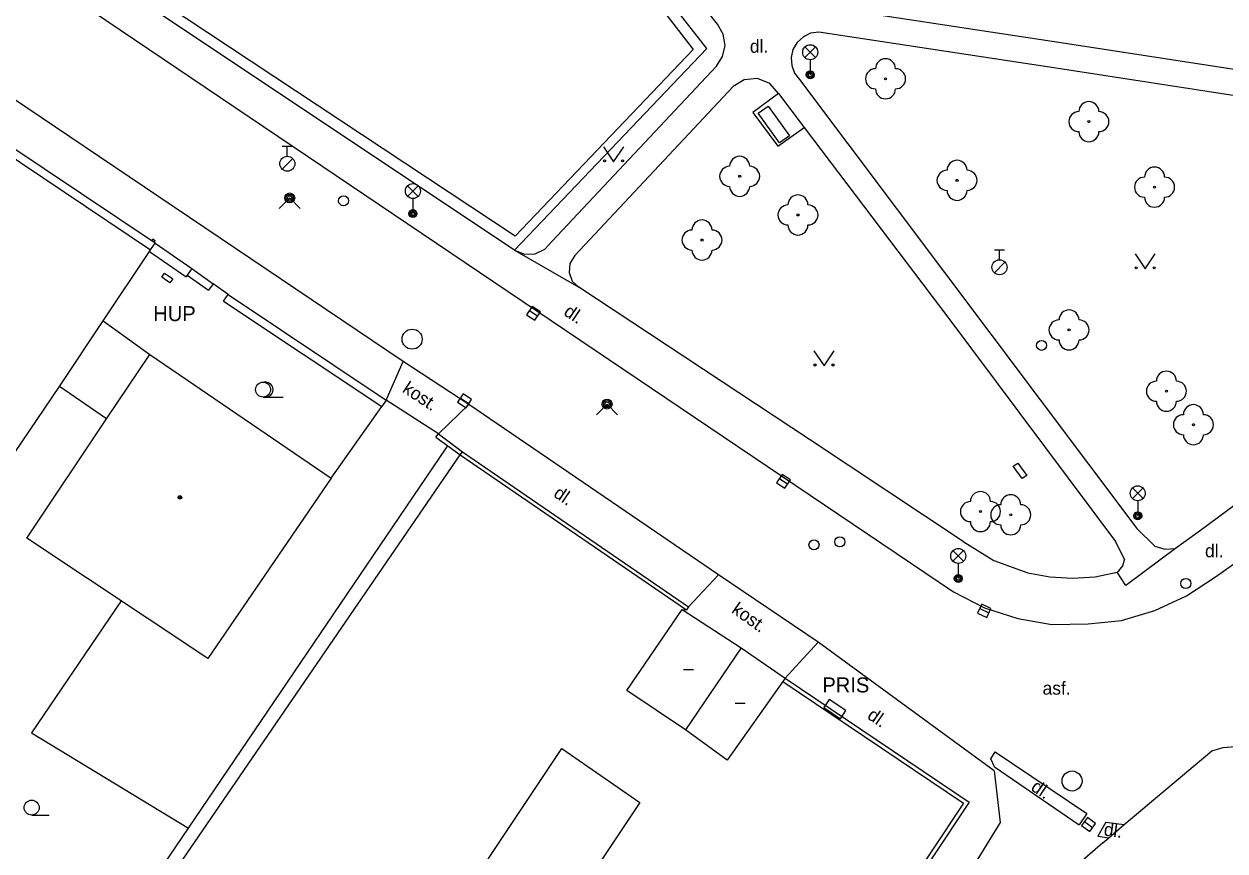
# Model space of a CAD drawing. Extents: x -600391 to -599491, y -1160176 to -1159402.
# Drawn here: x -600305.1 to -600245.1, y -1160114.6 to -1160073.3 of the extents above; entities that cross this region are included whole.
import ezdxf

# ---------------------------------------------------------------- set-up
doc = ezdxf.new("R2010")
doc.units = 0
for name, color, linetype in [('Level 10', 7, 'Continuous'), ('Level 11', 7, 'Continuous'), ('Level 22', 7, 'Continuous'), ('Level 24', 7, 'Continuous'), ('Level 27', 7, 'Continuous'), ('Level 28', 7, 'Continuous'), ('Level 31', 7, 'Continuous'), ('Level 33', 7, 'Continuous'), ('Level 36', 7, 'Continuous'), ('Level 39', 7, 'Continuous'), ('Level 40', 7, 'Continuous'), ('Level 41', 7, 'Continuous'), ('Level 5', 7, 'Continuous'), ('Level 7', 7, 'Continuous'), ('Level 8', 7, 'Continuous')]:
    doc.layers.add(name, color=color, linetype=linetype)

msp = doc.modelspace()

# ---------------------------------------------------------------- linework, layer by layer
at = {"layer": 'Level 10'}
for points in [[(-600391.008, -1160012.297), (-600389.33, -1160013.43), (-600385.97, -1160015.7), (-600380.12, -1160019.65), (-600376.77, -1160021.91), (-600369.66, -1160026.71), (-600367.22, -1160028.36), (-600362.33, -1160031.66), (-600357.66, -1160034.81), (-600345.98, -1160042.7), (-600342.95, -1160044.75), (-600341.58, -1160045.67), (-600338.1, -1160048.02), (-600335.29, -1160049.92), (-600325.8, -1160056.33), (-600315.13, -1160063.54), (-600309.38, -1160067.42), (-600304.6, -1160070.65), (-600301.7, -1160072.61), (-600258.67, -1160101.64)], [(-600286.14, -1160090.13), (-600298.33, -1160081.92), (-600327.82, -1160062.03), (-600331.39, -1160059.62), (-600334.69, -1160057.39), (-600338.31, -1160054.95), (-600376.99, -1160028.86)], [(-600256.63, -1160110.57), (-600265.43, -1160104.15), (-600270.39, -1160100.79), (-600282.86, -1160092.29), (-600286.14, -1160090.13)], [(-600245.58, -1160100.88), (-600242.67, -1160098.83)], [(-600258.67, -1160101.64), (-600257.12, -1160102.43), (-600255.46, -1160102.97), (-600253.75, -1160103.26), (-600251.95, -1160103.24), (-600250.28, -1160103.06), (-600248.61, -1160102.57), (-600247.03, -1160101.84), (-600245.58, -1160100.88)], [(-600245.77, -1160109.57), (-600245.2, -1160109.4), (-600244.19, -1160109.32)], [(-600251.22, -1160114.16), (-600250.92, -1160113.91), (-600250.14, -1160113.25), (-600245.77, -1160109.57)], [(-600256.63, -1160110.57), (-600256.34, -1160113.16), (-600267.47, -1160131.26)], [(-600251.22, -1160114.16), (-600254.94, -1160117.42), (-600259.81, -1160125.54), (-600260.41, -1160126.54), (-600260.93, -1160128.09), (-600260.66, -1160129.14), (-600260.06, -1160129.54), (-600259.92, -1160129.54)]]:
    msp.add_lwpolyline(points, dxfattribs=at)
at = {"layer": 'Level 11'}
for points in [[(-600270.44, -1160073.3), (-600270.89, -1160072.72), (-600279.69, -1160061.33), (-600280.7, -1160060.03), (-600290, -1160048.14)], [(-600268.21, -1160071.92), (-600253.19, -1160074.23), (-600244.65, -1160075.54), (-600243.72, -1160075.27)], [(-600270.5, -1160075.39), (-600270.19, -1160074.91), (-600270.07, -1160074.36), (-600270.16, -1160073.79), (-600270.44, -1160073.3)], [(-600265.39, -1160073.69), (-600265.8, -1160073.75), (-600266.16, -1160073.92), (-600266.47, -1160074.2), (-600266.68, -1160074.55), (-600266.77, -1160074.95), (-600266.74, -1160075.35), (-600266.6, -1160075.74), (-600266.35, -1160076.06)], [(-600242.12, -1160077.26), (-600253.45, -1160075.5), (-600265.39, -1160073.69)], [(-600278.7, -1160084.13), (-600270.5, -1160075.39)], [(-600277.57, -1160084.85), (-600269.67, -1160076.41)], [(-600267.4, -1160076.75), (-600267.84, -1160076.25), (-600268.45, -1160076.01), (-600269.11, -1160076.07), (-600269.67, -1160076.41)], [(-600266.35, -1160076.06), (-600249.51, -1160098.47)], [(-600267.4, -1160076.75), (-600268.68, -1160077.7), (-600267.43, -1160079.38), (-600266.12, -1160078.46)], [(-600267.4, -1160076.75), (-600266.12, -1160078.46)], [(-600266.86, -1160078.87), (-600267.35, -1160079.22), (-600268.41, -1160077.73), (-600267.92, -1160077.39)], [(-600267.92, -1160077.39), (-600266.86, -1160078.87)], [(-600266.12, -1160078.46), (-600258.9, -1160087.99)], [(-600280.58, -1160084.57), (-600280.08, -1160084.77), (-600279.54, -1160084.76), (-600279.06, -1160084.53), (-600278.7, -1160084.13)], [(-600280.58, -1160084.57), (-600277.37, -1160086.43)], [(-600277.57, -1160084.85), (-600277.81, -1160085.24), (-600277.85, -1160085.69), (-600277.7, -1160086.12), (-600277.37, -1160086.43)], [(-600258.19, -1160099.13), (-600265.85, -1160094.03), (-600277.37, -1160086.43)], [(-600301.12, -1160088.11), (-600298.78, -1160089.78)], [(-600258.9, -1160087.99), (-600250.58, -1160099.12)], [(-600286.99, -1160092.06), (-600286.14, -1160090.13)], [(-600235.08, -1160090.53), (-600244.15, -1160096.96), (-600246.33, -1160098.58), (-600247.58, -1160099.48)], [(-600300.94, -1160093), (-600303.29, -1160091.38)], [(-600289.73, -1160095.96), (-600287.21, -1160092.39)], [(-600282.86, -1160092.29), (-600284.38, -1160093.75)], [(-600311.37, -1160134.82), (-600296.86, -1160113.43), (-600283.99, -1160094.46), (-600283.91, -1160094.34)], [(-600249.51, -1160098.47), (-600248.61, -1160099.35)], [(-600258.19, -1160099.13), (-600256.65, -1160100.07), (-600254.96, -1160100.69), (-600253.85, -1160100.89), (-600252.72, -1160100.95), (-600251.6, -1160100.88), (-600250.49, -1160100.65)], [(-600250.58, -1160099.12), (-600250.13, -1160100.04)], [(-600247.58, -1160099.48), (-600250.06, -1160101.32), (-600250.49, -1160100.65)], [(-600248.61, -1160099.35), (-600248.11, -1160099.5), (-600247.58, -1160099.48)], [(-600250.49, -1160100.65), (-600250.42, -1160100.59), (-600250.22, -1160100.34), (-600250.13, -1160100.04)], [(-600271.89, -1160102.38), (-600270.39, -1160100.79)], [(-600300.22, -1160102.08), (-600304.69, -1160108.68), (-600296.86, -1160113.43)], [(-600272.21, -1160102.52), (-600272, -1160102.54)], [(-600265.43, -1160104.15), (-600267.07, -1160105.95)], [(-600256.8, -1160109.98), (-600256.59, -1160109.62), (-600252.01, -1160112.7), (-600252.4, -1160113.27)], [(-600256.62, -1160110.37), (-600256.8, -1160109.98)], [(-600256.62, -1160110.37), (-600252.4, -1160113.27)], [(-600251.06, -1160113.13), (-600251.46, -1160113.83)], [(-600251.06, -1160113.13), (-600250.14, -1160113.25)], [(-600251.46, -1160113.83), (-600250.92, -1160113.91)]]:
    msp.add_lwpolyline(points, dxfattribs=at)
at = {"layer": 'Level 22'}
for centre in [(-600262.06, -1160076.02), (-600251.91, -1160078.16), (-600269.34, -1160080.89), (-600258.49, -1160081.09), (-600248.63, -1160081.43), (-600266.43, -1160082.82), (-600271.22, -1160084.07), (-600252.9, -1160088.56), (-600248.04, -1160091.62), (-600246.69, -1160093.29), (-600257.32, -1160097.63), (-600255.81, -1160097.79)]:
    msp.add_circle(centre, 0.05, dxfattribs=at)
for centre, start, end in [((-600262.06, -1160075.52), 0, 180), ((-600262.56, -1160076.02), 90, 270), ((-600261.56, -1160076.02), 270, 90), ((-600262.06, -1160076.52), 180, 0), ((-600251.91, -1160077.66), 0, 180), ((-600252.41, -1160078.16), 90, 270), ((-600251.41, -1160078.16), 270, 90), ((-600251.91, -1160078.66), 180, 0), ((-600269.34, -1160080.39), 0, 180), ((-600269.84, -1160080.89), 90, 270), ((-600268.84, -1160080.89), 270, 90), ((-600258.99, -1160081.09), 90, 270), ((-600258.49, -1160080.59), 0, 180), ((-600257.99, -1160081.09), 270, 90), ((-600248.63, -1160080.93), 0, 180), ((-600249.13, -1160081.43), 90, 270), ((-600248.13, -1160081.43), 270, 90), ((-600269.34, -1160081.39), 180, 0), ((-600266.43, -1160082.32), 0, 180), ((-600258.49, -1160081.59), 180, 0), ((-600266.93, -1160082.82), 90, 270), ((-600265.93, -1160082.82), 270, 90), ((-600248.63, -1160081.93), 180, 0), ((-600271.72, -1160084.07), 90, 270), ((-600271.22, -1160083.57), 0, 180), ((-600270.72, -1160084.07), 270, 90), ((-600266.43, -1160083.32), 180, 0), ((-600271.22, -1160084.57), 180, 0), ((-600252.9, -1160088.06), 0, 180), ((-600253.4, -1160088.56), 90, 270), ((-600252.4, -1160088.56), 270, 90), ((-600252.9, -1160089.06), 180, 0), ((-600248.04, -1160091.12), 0, 180), ((-600248.54, -1160091.62), 90, 270), ((-600247.54, -1160091.62), 270, 90), ((-600248.04, -1160092.12), 180, 0), ((-600246.69, -1160092.79), 0, 180), ((-600247.19, -1160093.29), 90, 270), ((-600246.19, -1160093.29), 270, 90), ((-600246.69, -1160093.79), 180, 0), ((-600257.32, -1160097.13), 0, 180), ((-600255.81, -1160097.29), 0, 180), ((-600257.82, -1160097.63), 90, 270), ((-600256.82, -1160097.63), 270, 90), ((-600256.31, -1160097.79), 90, 270), ((-600255.31, -1160097.79), 270, 90), ((-600257.32, -1160098.13), 180, 0), ((-600255.81, -1160098.29), 180, 0)]:
    msp.add_arc(centre, 0.5, start, end, dxfattribs=at)
at = {"layer": 'Level 24'}
for points in [[(-600298.53, -1160084.09), (-600298.56, -1160084.2), (-600298.66, -1160084.12), (-600298.63, -1160084.01), (-600298.53, -1160084.09)], [(-600298.05, -1160085.72), (-600297.64, -1160086), (-600297.78, -1160086.21), (-600298.19, -1160085.93), (-600298.05, -1160085.72)], [(-600255.24, -1160095.97), (-600255.68, -1160095.36), (-600255.45, -1160095.21), (-600255.01, -1160095.82)], [(-600255.01, -1160095.82), (-600255.24, -1160095.97)]]:
    msp.add_lwpolyline(points, dxfattribs=at)
msp.add_lwpolyline([(-600265.144, -1160107.419), (-600264.315, -1160107.976), (-600264.036, -1160107.561), (-600264.865, -1160107.004)], close=True, dxfattribs=at)
at = {"layer": 'Level 27'}
for p, q in [((-600279.838, -1160087.592), (-600279.422, -1160087.868)), ((-600283.278, -1160091.962), (-600282.862, -1160092.238)), ((-600267.358, -1160095.982), (-600266.942, -1160096.258)), ((-600257.356, -1160102.474), (-600256.904, -1160102.686)), ((-600252.12, -1160113.101), (-600251.72, -1160113.399))]:
    msp.add_line(p, q, dxfattribs=at)
for points in [[(-600279.977, -1160087.8), (-600279.56, -1160088.077), (-600279.283, -1160087.66), (-600279.7, -1160087.383)], [(-600283.417, -1160092.17), (-600283, -1160092.447), (-600282.723, -1160092.03), (-600283.14, -1160091.753)], [(-600267.497, -1160096.19), (-600267.08, -1160096.467), (-600266.803, -1160096.05), (-600267.22, -1160095.773)], [(-600257.463, -1160102.7), (-600257.01, -1160102.913), (-600256.797, -1160102.46), (-600257.25, -1160102.247)], [(-600252.27, -1160113.301), (-600251.869, -1160113.6), (-600251.57, -1160113.199), (-600251.971, -1160112.9)]]:
    msp.add_lwpolyline(points, close=True, dxfattribs=at)
for centre in [(-600285.69, -1160089.02), (-600252.75, -1160111.08)]:
    msp.add_circle(centre, 0.5, dxfattribs=at)
at = {"layer": 'Level 28'}
for p, q in [((-600292.17, -1160079.385), (-600291.67, -1160079.385)), ((-600291.92, -1160079.885), (-600291.92, -1160079.385)), ((-600292.178, -1160080.532), (-600291.648, -1160080.002)), ((-600256.62, -1160084.555), (-600256.12, -1160084.555)), ((-600256.37, -1160085.055), (-600256.37, -1160084.555)), ((-600256.628, -1160085.702), (-600256.098, -1160085.172))]:
    msp.add_line(p, q, dxfattribs=at)
for centre, radius in [((-600291.92, -1160080.26), 0.375), ((-600289.11, -1160082.11), 0.25), ((-600256.37, -1160085.43), 0.375), ((-600264.34, -1160099.14), 0.25), ((-600247.07, -1160101.22), 0.25)]:
    msp.add_circle(centre, radius, dxfattribs=at)
at = {"layer": 'Level 31'}
for points in [[(-600292.33, -1160082.5), (-600291.8, -1160081.97), (-600291.27, -1160082.5)], [(-600276.49, -1160092.79), (-600275.96, -1160092.26), (-600275.43, -1160092.79)]]:
    msp.add_lwpolyline(points, dxfattribs=at)
for centre, radius in [((-600291.8, -1160081.97), 0.25), ((-600291.8, -1160081.97), 0.18), ((-600291.8, -1160081.97), 0.11), ((-600254.27, -1160089.33), 0.25), ((-600275.96, -1160092.26), 0.25), ((-600275.96, -1160092.26), 0.18), ((-600275.96, -1160092.26), 0.11), ((-600265.63, -1160099.29), 0.25)]:
    msp.add_circle(centre, radius, dxfattribs=at)
at = {"layer": 'Level 33'}
for p, q in [((-600266.085, -1160074.96), (-600265.555, -1160074.43)), ((-600266.085, -1160074.43), (-600265.555, -1160074.96)), ((-600265.82, -1160075.07), (-600265.82, -1160075.82)), ((-600285.915, -1160081.89), (-600285.385, -1160081.36)), ((-600285.915, -1160081.36), (-600285.385, -1160081.89)), ((-600285.65, -1160082), (-600285.65, -1160082.75)), ((-600249.735, -1160096.98), (-600249.205, -1160096.45)), ((-600249.735, -1160096.45), (-600249.205, -1160096.98)), ((-600249.47, -1160097.09), (-600249.47, -1160097.84)), ((-600258.695, -1160100.11), (-600258.165, -1160099.58)), ((-600258.695, -1160099.58), (-600258.165, -1160100.11)), ((-600258.43, -1160100.22), (-600258.43, -1160100.97))]:
    msp.add_line(p, q, dxfattribs=at)
for centre, radius in [((-600265.82, -1160074.695), 0.375), ((-600265.82, -1160075.82), 0.2), ((-600265.82, -1160075.82), 0.145), ((-600265.82, -1160075.82), 0.0876), ((-600285.65, -1160081.625), 0.375), ((-600285.65, -1160082.75), 0.2), ((-600285.65, -1160082.75), 0.145), ((-600285.65, -1160082.75), 0.0876), ((-600249.47, -1160096.715), 0.375), ((-600249.47, -1160097.84), 0.2), ((-600249.47, -1160097.84), 0.145), ((-600249.47, -1160097.84), 0.0876), ((-600258.43, -1160099.845), 0.375), ((-600258.43, -1160100.97), 0.2), ((-600258.43, -1160100.97), 0.145), ((-600258.43, -1160100.97), 0.0876)]:
    msp.add_circle(centre, radius, dxfattribs=at)
at = {"layer": 'Level 36'}
for p, q in [((-600293.13, -1160091.915), (-600292.13, -1160091.915)), ((-600304.68, -1160112.785), (-600303.805, -1160112.785))]:
    msp.add_line(p, q, dxfattribs=at)
for points in [[(-600276.13, -1160079.42), (-600275.63, -1160080.17), (-600275.13, -1160079.42)], [(-600249.6, -1160084.76), (-600249.1, -1160085.51), (-600248.6, -1160084.76)], [(-600265.63, -1160089.61), (-600265.13, -1160090.36), (-600264.63, -1160089.61)]]:
    msp.add_lwpolyline(points, dxfattribs=at)
for centre, radius in [((-600276.08, -1160080.12), 0.05), ((-600275.181, -1160080.12), 0.05), ((-600249.55, -1160085.46), 0.05), ((-600248.651, -1160085.46), 0.05), ((-600265.58, -1160090.31), 0.05), ((-600264.681, -1160090.31), 0.05), ((-600293.13, -1160091.54), 0.375), ((-600304.68, -1160112.41), 0.375)]:
    msp.add_circle(centre, radius, dxfattribs=at)
msp.add_arc((-600293.005, -1160091.54), 0.375, 260.40593, 99.59407, dxfattribs=at)
at = {"layer": 'Level 39'}
for p, q in [((-600272.14, -1160105.52), (-600271.64, -1160105.52)), ((-600269.57, -1160107.19), (-600269.07, -1160107.19))]:
    msp.add_line(p, q, dxfattribs=at)
for radius in [0.09, 0.0398]:
    msp.add_circle((-600297.28, -1160096.92), radius, dxfattribs=at)
at = {"layer": 'Level 5'}
for points in [[(-600300.94, -1160093), (-600298.78, -1160089.78)], [(-600298.78, -1160089.78), (-600289.73, -1160095.96)], [(-600304.92, -1160098.95), (-600300.94, -1160093)], [(-600289.73, -1160095.96), (-600295.89, -1160104.97)], [(-600295.89, -1160104.97), (-600304.92, -1160098.95)], [(-600274.98, -1160106.56), (-600272.21, -1160102.52)], [(-600272.21, -1160102.52), (-600269.27, -1160104.43)], [(-600269.27, -1160104.43), (-600272.05, -1160108.53)], [(-600269.27, -1160104.43), (-600267.07, -1160105.95)], [(-600267.07, -1160105.95), (-600267.19, -1160106.12), (-600269.96, -1160110.04)], [(-600272.05, -1160108.53), (-600274.98, -1160106.56)], [(-600269.96, -1160110.04), (-600272.05, -1160108.53)], [(-600285.49, -1160120.38), (-600278.22, -1160109.45)], [(-600278.22, -1160109.45), (-600274.33, -1160112.15)], [(-600274.33, -1160112.15), (-600285.69, -1160129.22)]]:
    msp.add_lwpolyline(points, dxfattribs=at)
at = {"layer": 'Level 7'}
for points in [[(-600291.19, -1160048.68), (-600291.46, -1160048.9), (-600271.66, -1160074.55), (-600280.55, -1160083.87), (-600298.1, -1160072.26)], [(-600280.58, -1160084.57), (-600270.98, -1160074.51), (-600291, -1160048.92)], [(-600280.58, -1160084.57), (-600298.53, -1160072.61)], [(-600298.8, -1160084.64), (-600298.75, -1160084.56), (-600298.52, -1160084.23), (-600311.48, -1160075.55), (-600311.7, -1160075.88)], [(-600311.7, -1160075.88), (-600298.75, -1160084.56)], [(-600298.52, -1160084.23), (-600296.69, -1160085.49)], [(-600301.12, -1160088.11), (-600298.8, -1160084.64)], [(-600298.8, -1160084.64), (-600296.97, -1160085.9)], [(-600296.69, -1160085.49), (-600296.92, -1160085.82), (-600296.97, -1160085.9)], [(-600296.92, -1160085.82), (-600295.85, -1160086.58)], [(-600296.69, -1160085.49), (-600295.62, -1160086.25), (-600295.85, -1160086.58)], [(-600295.1, -1160087.12), (-600294.88, -1160086.79)], [(-600295.1, -1160087.12), (-600287.21, -1160092.39)], [(-600294.88, -1160086.79), (-600286.99, -1160092.06), (-600287.21, -1160092.39)], [(-600303.29, -1160091.38), (-600301.12, -1160088.11)], [(-600326.08, -1160125.06), (-600325.98, -1160124.91), (-600303.29, -1160091.38)], [(-600284.5, -1160093.91), (-600284.38, -1160093.75), (-600283.18, -1160094.64)], [(-600284.5, -1160093.91), (-600283.91, -1160094.34), (-600283.29, -1160094.8)], [(-600301.23, -1160120.97), (-600283.29, -1160094.8)], [(-600283.29, -1160094.8), (-600283.18, -1160094.64)], [(-600283.29, -1160094.8), (-600272, -1160102.54)], [(-600283.18, -1160094.64), (-600271.89, -1160102.38)], [(-600271.89, -1160102.38), (-600272, -1160102.54)], [(-600267.19, -1160106.12), (-600258.16, -1160112.18), (-600271.08, -1160131.63), (-600276.02, -1160138.96)], [(-600267.07, -1160105.95), (-600257.88, -1160112.13)], [(-600257.88, -1160112.13), (-600270.91, -1160131.74)]]:
    msp.add_lwpolyline(points, dxfattribs=at)
at = {"layer": 'Level 8'}
for points in [[(-600294.88, -1160086.79), (-600295.62, -1160086.25)], [(-600284.38, -1160093.75), (-600286.99, -1160092.06)]]:
    msp.add_lwpolyline(points, dxfattribs=at)

# ---------------------------------------------------------------- texts
at = {"layer": 'Level 40'}
for s, p in [('dl.', (-600268.83, -1160074.72)), ('dl.', (-600268.83, -1160074.72)), ('dl.', (-600246.11, -1160099.91)), ('dl.', (-600246.11, -1160099.91)), ('asf.', (-600254.22, -1160106.77)), ('asf.', (-600254.22, -1160106.77))]:
    msp.add_text(s, height=0.65, dxfattribs=at).set_placement(p)
for s, rotation, p in [('dl.', 325.98291, (-600278.17, -1160087.78)), ('kost.', 326.63363, (-600286.22, -1160091.63)), ('dl.', 325.98572, (-600278.68, -1160096.85)), ('kost.', 324.59647, (-600269.79, -1160102.64)), ('dl.', 325.98572, (-600263.02, -1160107.93)), ('dl.', 326.0796, (-600254.85, -1160111.51)), ('dl.', 352.37185, (-600251.19, -1160113.8))]:
    msp.add_text(s, height=0.65, rotation=rotation, dxfattribs=at).set_placement(p)
at = {"layer": 'Level 41'}
for s, p in [('HUP', (-600298.61, -1160088.12)), ('PRIS', (-600265.21, -1160106.66))]:
    msp.add_text(s, height=0.75, dxfattribs=at).set_placement(p)

doc.saveas('drawing.dxf')
